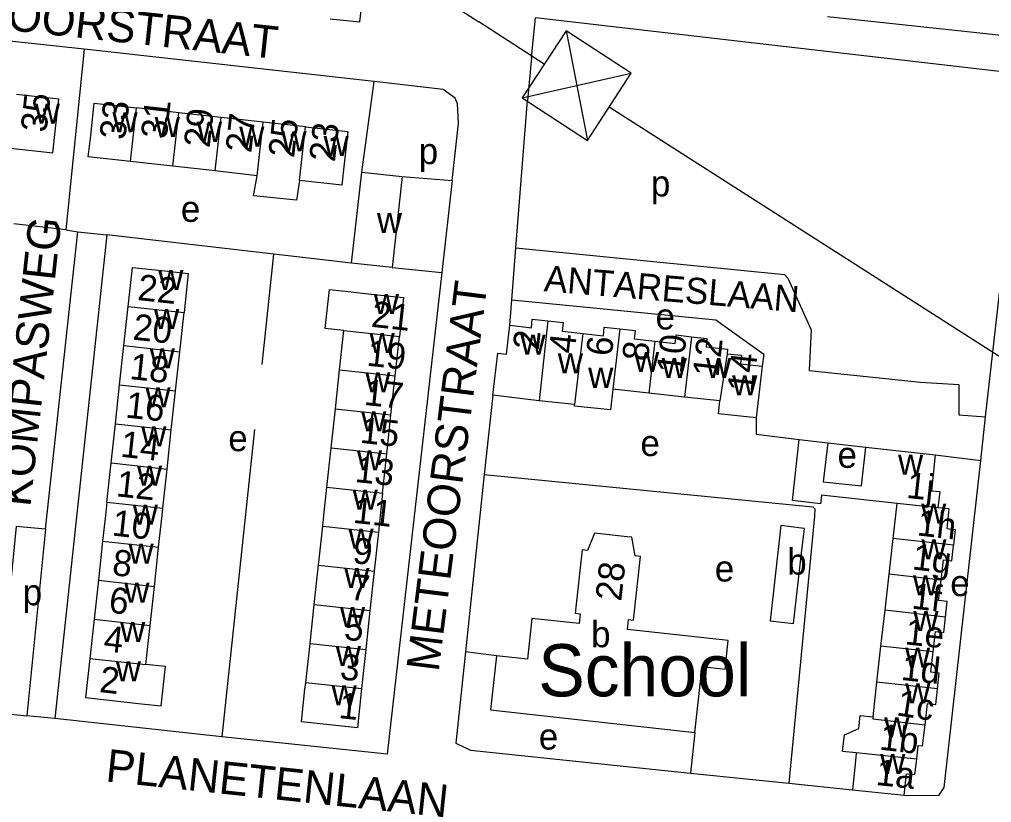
# Model space of a CAD drawing. Extents: x 161936 to 163647, y 386450 to 388633.
# Drawn here: x 162379.9 to 162529.2, y 386956 to 387076.1 of the extents above; entities that cross this region are included whole.
import ezdxf

# ---------------------------------------------------------------- set-up
doc = ezdxf.new("R2010")
doc.units = 0
for name, color, linetype in [('BLT_Basislijn', 7, 'Continuous'), ('BLT_Bebouwing', 7, 'Continuous'), ('BLT_Bebouwing_beschrifting', 7, 'Continuous'), ('BLT_Centroide', 7, 'Continuous'), ('BLT_Hoogspanningsmast_en_leidingen', 7, 'Continuous'), ('BLT_Huisnummer', 7, 'Continuous'), ('BLT_Huisnummer_ tussenligend', 7, 'Continuous'), ('BLT_Onderverdeling_panden', 7, 'Continuous'), ('BLT_Straatnaam', 7, 'Continuous'), ('BLT_Straatnaam_verkleind', 7, 'Continuous')]:
    doc.layers.add(name, color=color, linetype=linetype)

msp = doc.modelspace()

# ---------------------------------------------------------------- linework, layer by layer
at = {"layer": 'BLT_Basislijn'}
for p, q in [((162458.53, 387070.29), (162459.14, 387076.37)), ((162534.16, 387067.72), (162459.14, 387076.37)), ((162503.95, 387076.6), (162534.81, 387073.29)), ((162389.85, 387071.58), (162387.06, 387043.88)), ((162434.36, 387066.62), (162389.85, 387071.58)), ((162458.53, 387070.29), (162457.91, 387063.68)), ((162528.24, 387015.15), (162534.16, 387067.72)), ((162432.48, 387052.73), (162434.36, 387066.62)), ((162456.14, 387041.07), (162457.91, 387063.68)), ((162438.7, 387052.03), (162446.33, 387051.42)), ((162446.33, 387051.42), (162444.75, 387037.3)), ((162387.06, 387043.88), (162379.07, 387044.79)), ((162387.06, 387043.88), (162388.89, 387043.56)), ((162383.91, 386997.91), (162388.89, 387043.56)), ((162393.36, 387043.09), (162385.37, 386968.87)), ((162388.89, 387043.56), (162393.36, 387043.09)), ((162419, 387040.14), (162393.36, 387043.09)), ((162455.52, 387033.09), (162456.14, 387041.07)), ((162417.18, 387023.18), (162419, 387040.14)), ((162430.9, 387038.76), (162419, 387040.14)), ((162437.12, 387038.06), (162444.75, 387037.3)), ((162455.22, 387029.22), (162455.52, 387033.09)), ((162452.62, 387018.51), (162451.29, 387006.33)), ((162416.02, 387013.22), (162411.02, 386966.03)), ((162520.48, 387009.34), (162527.5, 387008.46)), ((162451.29, 387006.33), (162448.39, 386979.09)), ((162383.91, 386997.91), (162381.05, 386969.29)), ((162453.14, 386978.5), (162448.39, 386979.09)), ((162376.57, 386969.75), (162381.05, 386969.29)), ((162385.37, 386968.87), (162381.05, 386969.29)), ((162411.02, 386966.03), (162385.37, 386968.87)), ((162483.61, 386966.71), (162482.95, 386960.5)), ((162482.95, 386960.5), (162498.03, 386958.94)), ((162498.03, 386958.94), (162507.79, 386957.93))]:
    msp.add_line(p, q, dxfattribs=at)
for points in [[(162427.61, 387076.25), (162432.17, 387075.76), (162432.94, 387082.3)], [(162389.85, 387071.58), (162333.1, 387077.67)], [(162446.33, 387051.42), (162447.35, 387060.19), (162447.17, 387063.2), (162446.84, 387064.07), (162444.99, 387065.38), (162434.36, 387066.62)], [(162456.14, 387041.07), (162497.35, 387037), (162497.86, 387036.45), (162501.46, 387028.53), (162501.17, 387022.29), (162518.24, 387020.47), (162524.16, 387020.1), (162524.12, 387015.48), (162528.24, 387015.15)], [(162444.75, 387037.3), (162436.4, 386963.4), (162411.02, 386966.03)], [(162455.52, 387033.09), (162486.85, 387030.05), (162494.21, 387024.76), (162493.94, 387022.93)], [(162493.04, 387014.99), (162493.02, 387012.48), (162499.63, 387011.68)], [(162527.5, 387008.46), (162528.24, 387015.15)], [(162504.03, 387011.19), (162509.84, 387010.49)], [(162515.74, 386957.1), (162521.09, 386957.06), (162521.89, 386958.3), (162527.5, 387008.46)], [(162451.29, 387006.33), (162501.74, 387001.35), (162502.01, 387001.06), (162501.98, 386999.91), (162498.03, 386958.94)], [(162383.91, 386997.91), (162379.42, 386998.33), (162376.57, 386969.75)], [(162448.39, 386979.09), (162446.9, 386965.06), (162449.19, 386964), (162482.95, 386960.5)]]:
    msp.add_lwpolyline(points, dxfattribs=at)
at = {"layer": 'BLT_Bebouwing'}
for p, q in [((162404.39, 387061.83), (162397.9, 387062.56)), ((162410.88, 387061.11), (162404.39, 387061.83)), ((162417.36, 387060.38), (162410.88, 387061.11)), ((162423.85, 387059.65), (162417.36, 387060.38)), ((162403.47, 387053.61), (162396.98, 387054.34)), ((162409.96, 387052.89), (162403.47, 387053.61)), ((162416.44, 387052.16), (162409.96, 387052.89)), ((162430.9, 387038.76), (162432.48, 387052.73)), ((162432.48, 387052.73), (162438.7, 387052.03)), ((162438.7, 387052.03), (162437.12, 387038.06)), ((162437.12, 387038.06), (162430.9, 387038.76)), ((162395.96, 387026.09), (162396.61, 387032.09)), ((162404.55, 387025.15), (162405.2, 387031.15)), ((162429.08, 387022.39), (162429.73, 387028.39)), ((162437.61, 387021.46), (162438.25, 387027.47)), ((162395.3, 387020.09), (162395.96, 387026.09)), ((162403.9, 387019.15), (162404.55, 387025.15)), ((162493.94, 387022.93), (162493.04, 387014.99)), ((162428.43, 387016.39), (162429.08, 387022.39)), ((162436.96, 387015.46), (162437.61, 387021.46)), ((162394.65, 387014.09), (162395.3, 387020.09)), ((162403.24, 387013.15), (162403.9, 387019.15)), ((162476.55, 387018.8), (162471.03, 387019.41)), ((162482.04, 387018.2), (162476.55, 387018.8)), ((162465.16, 387017.03), (162459.71, 387017.63)), ((162487.44, 387017.61), (162482.04, 387018.2)), ((162427.78, 387010.39), (162428.43, 387016.39)), ((162436.32, 387009.46), (162436.96, 387015.46)), ((162394, 387008.09), (162394.65, 387014.09)), ((162402.59, 387007.15), (162403.24, 387013.15)), ((162427.13, 387004.39), (162427.78, 387010.39)), ((162393.35, 387002.09), (162394, 387008.09)), ((162435.67, 387003.46), (162436.32, 387009.46)), ((162401.94, 387001.15), (162402.59, 387007.15)), ((162514.04, 386996.5), (162514.65, 387001.88)), ((162522.61, 387001.02), (162520.9, 387001.2)), ((162425.83, 386992.38), (162426.48, 386998.38)), ((162392.7, 386996.09), (162392.05, 386990.09)), ((162435.03, 386997.46), (162434.38, 386991.46)), ((162513.43, 386991.04), (162514.04, 386996.5)), ((162400.64, 386989.15), (162401.29, 386995.15)), ((162425.18, 386986.38), (162425.83, 386992.38)), ((162392.05, 386990.09), (162391.4, 386984.09)), ((162434.38, 386991.46), (162433.74, 386985.46)), ((162512.81, 386985.5), (162513.43, 386991.04)), ((162399.99, 386983.15), (162400.64, 386989.15)), ((162424.53, 386980.38), (162425.18, 386986.38)), ((162433.74, 386985.46), (162433.09, 386979.45)), ((162512.18, 386979.95), (162512.81, 386985.5)), ((162391.4, 386984.09), (162390.75, 386978.09)), ((162399.34, 386977.15), (162399.99, 386983.15)), ((162423.88, 386974.38), (162424.53, 386980.38)), ((162511.56, 386974.45), (162512.18, 386979.95)), ((162433.09, 386979.45), (162432.44, 386973.45)), ((162510.96, 386969.11), (162511.56, 386974.45)), ((162507.79, 386957.93), (162515.74, 386957.1))]:
    msp.add_line(p, q, dxfattribs=at)
for points in [[(162378.57, 387056.39), (162385.03, 387055.67), (162385.39, 387058.94), (162385.95, 387063.91), (162379.49, 387064.63)], [(162396.98, 387054.34), (162390.49, 387055.06), (162390.86, 387058.31), (162391.41, 387063.28), (162397.9, 387062.56)], [(162423.85, 387059.65), (162430.33, 387058.93), (162429.78, 387053.96), (162429.42, 387050.71), (162422.93, 387051.44)], [(162422.93, 387051.44), (162422.44, 387048.43), (162415.87, 387049.08), (162416.44, 387052.16)], [(162396.61, 387032.09), (162397.26, 387038.09), (162402.23, 387037.55), (162405.85, 387037.15), (162405.2, 387031.15)], [(162429.73, 387028.39), (162426.85, 387028.7), (162427.5, 387034.7), (162430.39, 387034.39), (162433.93, 387034.01), (162438.9, 387033.47), (162438.25, 387027.47)], [(162452.62, 387018.51), (162453.37, 387024.95), (162454.72, 387024.79), (162455.22, 387029.22)], [(162455.22, 387029.22), (162458.51, 387028.84), (162458.65, 387030.14), (162461.03, 387029.88)], [(162461.03, 387029.88), (162463.42, 387029.62), (162463.26, 387028.32), (162466.41, 387027.96)], [(162466.41, 387027.96), (162469.57, 387027.59), (162469.7, 387028.93), (162472.08, 387028.67)], [(162472.08, 387028.67), (162474.46, 387028.42), (162474.31, 387027.12), (162477.45, 387026.78)], [(162477.45, 387026.78), (162480.59, 387026.44), (162480.72, 387027.72), (162483.09, 387027.44)], [(162483.09, 387027.44), (162485.47, 387027.17), (162485.36, 387025.88), (162488.61, 387025.52), (162488.57, 387024.82)], [(162488.57, 387024.82), (162490.78, 387024.6), (162490.64, 387023.3), (162493.94, 387022.93)], [(162459.71, 387017.63), (162452.62, 387018.51)], [(162471.03, 387019.41), (162470.67, 387016.21), (162465.15, 387016.81), (162465.16, 387017.03)], [(162493.04, 387014.99), (162487.22, 387015.62), (162487.44, 387017.61)], [(162498.6, 387002.32), (162499.63, 387011.68)], [(162499.63, 387011.68), (162504.03, 387011.19)], [(162504.03, 387011.19), (162503.3, 387005.17), (162509.2, 387004.59), (162509.84, 387010.49)], [(162509.84, 387010.49), (162520.48, 387009.34)], [(162520.48, 387009.34), (162519.93, 387003.82), (162521.22, 387003.7), (162520.9, 387001.2)], [(162426.48, 386998.38), (162426.66, 387000), (162427.13, 387004.39)], [(162393.35, 387002.09), (162393.12, 387000), (162392.7, 386996.09)], [(162435.67, 387003.46), (162435.3, 387000), (162435.03, 386997.46)], [(162514.65, 387001.88), (162503.05, 387003.14), (162502.89, 387001.81), (162498.6, 387002.32)], [(162401.29, 386995.15), (162401.82, 387000), (162401.94, 387001.15)], [(162522.61, 387001.02), (162522.51, 387000), (162522.3, 386998.01), (162523.57, 386997.87), (162523.31, 386995.48)], [(162500, 386998.1), (162496.81, 386998.46), (162495.17, 386983.87), (162498.78, 386983.47), (162500, 386994.25), (162500.43, 386998.05), (162500, 386998.1)], [(162473.27, 386982.53), (162473.44, 386984.05), (162474.17, 386983.97), (162475.25, 386993.72), (162474.43, 386993.81), (162473.93, 386996.67), (162473.2, 386996.76), (162468.23, 386997.3), (162467.15, 386994.66), (162466.29, 386994.75), (162465.22, 386985.01), (162466.02, 386984.92), (162465.86, 386983.43)], [(162521.4, 386990.1), (162521.77, 386993.21), (162523.04, 386993.08), (162523.31, 386995.48)], [(162522.08, 386984.44), (162522.36, 386986.83), (162521.03, 386986.99), (162521.4, 386990.1)], [(162465.86, 386983.43), (162458.6, 386984.23), (162457.91, 386977.98), (162453.14, 386978.5)], [(162520.19, 386979.09), (162520.53, 386982.21), (162521.81, 386982.05), (162522.08, 386984.44)], [(162483.61, 386966.71), (162484.72, 386976.83), (162488.26, 386976.44), (162488.74, 386980.83), (162473.27, 386982.53)], [(162453.14, 386978.5), (162452.23, 386970.22), (162483.61, 386966.71)], [(162520.88, 386973.42), (162521.14, 386975.8), (162519.86, 386975.97), (162520.19, 386979.09)], [(162390.75, 386978.09), (162390.09, 386972.08), (162398.68, 386971.12), (162401.68, 386970.79), (162402.34, 386976.83), (162399.34, 386977.15)], [(162432.44, 386973.45), (162431.8, 386967.45), (162423.23, 386968.38), (162423.76, 386973.35), (162423.88, 386974.38)], [(162518.95, 386967.92), (162519.32, 386971.18), (162520.62, 386971.04), (162520.88, 386973.42)], [(162508.38, 386963.61), (162506.29, 386963.83), (162506.56, 386966.36), (162508.77, 386967.31), (162508.97, 386969.32), (162510.96, 386969.11)], [(162517.67, 386962.63), (162517.91, 386964.73), (162518.57, 386964.65), (162518.95, 386967.92)], [(162508.38, 386963.61), (162508.31, 386962.9), (162507.79, 386957.93)], [(162515.74, 386957.1), (162516.09, 386960.4), (162517.4, 386960.26), (162517.67, 386962.63)]]:
    msp.add_lwpolyline(points, dxfattribs=at)
at = {"layer": 'BLT_Hoogspanningsmast_en_leidingen'}
for p, q in [((162209.53, 387230.13), (162450.47, 387075.79)), ((162460.47, 387069.27), (162450.47, 387075.79)), ((162463.83, 387074.42), (162467.11, 387057.59)), ((162457.11, 387064.11), (162473.83, 387067.9)), ((162470.47, 387062.75), (162726.36, 386899.12))]:
    msp.add_line(p, q, dxfattribs=at)
msp.add_lwpolyline([(162463.83, 387074.42), (162457.11, 387064.11), (162467.11, 387057.59), (162473.83, 387067.9)], close=True, dxfattribs=at)
at = {"layer": 'BLT_Onderverdeling_panden'}
for p, q in [((162396.98, 387054.34), (162397.9, 387062.56)), ((162403.47, 387053.61), (162404.39, 387061.83)), ((162409.96, 387052.89), (162410.88, 387061.11)), ((162416.44, 387052.16), (162417.36, 387060.38)), ((162422.93, 387051.44), (162423.85, 387059.65)), ((162396.61, 387032.09), (162405.2, 387031.15)), ((162461.03, 387029.88), (162459.71, 387017.63)), ((162429.73, 387028.39), (162438.25, 387027.47)), ((162466.41, 387027.96), (162465.16, 387017.03)), ((162472.08, 387028.67), (162471.03, 387019.41)), ((162483.09, 387027.44), (162482.04, 387018.2)), ((162395.96, 387026.09), (162404.55, 387025.15)), ((162477.45, 387026.78), (162476.55, 387018.8)), ((162488.57, 387024.82), (162487.44, 387017.61)), ((162429.08, 387022.39), (162437.61, 387021.46)), ((162395.3, 387020.09), (162403.9, 387019.15)), ((162428.43, 387016.39), (162436.96, 387015.46)), ((162394.65, 387014.09), (162403.24, 387013.15)), ((162427.78, 387010.39), (162436.32, 387009.46)), ((162394, 387008.09), (162402.59, 387007.15)), ((162427.13, 387004.39), (162435.67, 387003.46)), ((162393.35, 387002.09), (162401.94, 387001.15)), ((162520.9, 387001.2), (162514.65, 387001.88)), ((162426.48, 386998.38), (162435.03, 386997.46)), ((162392.7, 386996.09), (162401.29, 386995.15)), ((162523.31, 386995.48), (162514.04, 386996.5)), ((162425.83, 386992.38), (162434.38, 386991.46)), ((162392.05, 386990.09), (162400.64, 386989.15)), ((162521.4, 386990.1), (162513.43, 386991.04)), ((162425.18, 386986.38), (162433.74, 386985.46)), ((162522.08, 386984.44), (162512.81, 386985.5)), ((162391.4, 386984.09), (162399.99, 386983.15)), ((162424.53, 386980.38), (162433.09, 386979.45)), ((162520.19, 386979.09), (162512.18, 386979.95)), ((162390.75, 386978.09), (162399.34, 386977.15)), ((162423.88, 386974.38), (162432.44, 386973.45)), ((162520.88, 386973.42), (162511.56, 386974.45)), ((162517.67, 386962.63), (162508.38, 386963.61))]:
    msp.add_line(p, q, dxfattribs=at)
msp.add_lwpolyline([(162510.96, 386969.11), (162510.93, 386968.84), (162518.95, 386967.92)], dxfattribs=at)

# ---------------------------------------------------------------- texts
at = {"layer": 'BLT_Bebouwing_beschrifting'}
msp.add_text('School', height=8, dxfattribs=at).set_placement((162459.57, 386972.27))
at = {"layer": 'BLT_Centroide'}
for s, p in [('w', (162382.27, 387060.14)), ('w', (162394.2, 387058.81)), ('w', (162400.69, 387058.09)), ('w', (162407.17, 387057.36)), ('w', (162413.66, 387056.62)), ('w', (162420.14, 387055.91)), ('w', (162426.62, 387055.19)), ('p', (162441.23, 387053.94)), ('p', (162476.87, 387048.98)), ('e', (162404.71, 387045.08)), ('w', (162434.8, 387043.39)), ('w', (162401.23, 387034.62)), ('w', (162434.32, 387030.94)), ('w', (162400.58, 387028.62)), ('e', (162477.58, 387028.57)), ('w', (162433.67, 387024.94)), ('w', (162456.83, 387024.72)), ('w', (162399.92, 387022.62)), ('w', (162462.57, 387021.82)), ('w', (162474.27, 387022.06)), ('w', (162478.52, 387021.13)), ('w', (162485.33, 387021.13)), ('w', (162433.02, 387018.94)), ('w', (162467.23, 387019.61)), ('w', (162489.34, 387018.45)), ('w', (162399.27, 387016.62)), ('w', (162432.38, 387012.94)), ('w', (162398.62, 387010.62)), ('e', (162411.99, 387009.89)), ('e', (162475.26, 387009.14)), ('w', (162431.73, 387006.94)), ('e', (162505.52, 387007.33)), ('w', (162514.8, 387006.28)), ('w', (162397.97, 387004.62)), ('w', (162431.07, 387000.91)), ('w', (162397.32, 386998.62)), ('w', (162518.34, 386998.78)), ('w', (162430.43, 386994.91)), ('w', (162518.38, 386993.31)), ('w', (162396.67, 386992.62)), ('b', (162497.8, 386990.95)), ('w', (162429.78, 386988.91)), ('e', (162486.67, 386989.89)), ('w', (162517.09, 386987.75)), ('e', (162522.82, 386987.65)), ('p', (162380.43, 386986.24)), ('w', (162396.02, 386986.62)), ('w', (162429.13, 386982.91)), ('w', (162517.15, 386982.28)), ('w', (162395.37, 386980.62)), ('b', (162467.69, 386979.81)), ('w', (162428.48, 386976.91)), ('w', (162515.88, 386976.69)), ('w', (162394.72, 386974.59)), ('w', (162427.84, 386970.91)), ('w', (162515.91, 386971.19)), ('w', (162512.68, 386965.97)), ('e', (162459.66, 386964.1)), ('w', (162512.06, 386960.34))]:
    msp.add_text(s, height=4, dxfattribs=at).set_placement(p)
at = {"layer": 'BLT_Huisnummer'}
for s, rotation, p in [('35', 83.6142, (162384.06, 387058.71)), ('33', 83.6185, (162396.16, 387057.58)), ('27', 83.6185, (162415.51, 387055.57)), ('23', 83.6269, (162428.35, 387054.17)), ('22', 353.8084, (162397.94, 387033.1)), ('21', 353.8111, (162433.82, 387028.99)), ('2', 83.8553, (162459.63, 387025.29)), ('10', 83.4769, (162481.69, 387021.67)), ('6', 83.7898, (162470.86, 387024.36)), ('18', 353.8084, (162396.74, 387020.97)), ('14', 83.5608, (162492.56, 387018.82)), ('17', 353.8117, (162432.73, 387017.01)), ('14', 353.8084, (162395.32, 387009.05)), ('13', 353.8087, (162431.33, 387005.18)), ('1j', 353.8258, (162515.98, 387002.74)), ('10', 353.8077, (162394.02, 386996.96)), ('9', 353.8123, (162430.95, 386992.73)), ('1g', 353.2814, (162516.86, 386991.77)), ('28', 83.7158, (162472.31, 386986.77)), ('6', 353.8077, (162393.53, 386985.12)), ('5', 353.8091, (162429.64, 386980.98)), ('1e', 353.8711, (162515.76, 386980.26)), ('2', 353.6283, (162392.09, 386972.94)), ('1', 353.8359, (162428.83, 386968.95)), ('1c', 350.942, (162514.43, 386969.38)), ('1a', 354.0592, (162511.28, 386958.68))]:
    msp.add_text(s, height=4, rotation=rotation, dxfattribs=at).set_placement(p)
at = {"layer": 'BLT_Huisnummer_ tussenligend'}
for s, rotation, p in [('31', 83.6185, (162402.51, 387057.69)), ('29', 83.6185, (162409.11, 387056.35)), ('25', 83.6269, (162422.08, 387054.81)), ('20', 353.8084, (162397.22, 387027.02)), ('4', 83.8553, (162465.16, 387024.76)), ('19', 353.8117, (162433.13, 387023.03)), ('8', 83.7898, (162476.4, 387023.59)), ('12', 83.4769, (162487.23, 387021.17)), ('16', 353.8084, (162396.09, 387015.07)), ('15', 353.8087, (162432.1, 387011.19)), ('12', 353.8077, (162394.67, 387002.98)), ('11', 353.8123, (162431.03, 386998.91)), ('1h', 353.7094, (162517.61, 386996.98)), ('8', 353.8077, (162394.05, 386990.88)), ('7', 353.8091, (162430.52, 386987.12)), ('1f', 353.4924, (162516.78, 386985.75)), ('4', 353.6283, (162392.72, 386979.21)), ('3', 353.8359, (162429.02, 386974.88)), ('1d', 353.7132, (162515.15, 386974.8)), ('1b', 353.4295, (162511.83, 386964.11))]:
    msp.add_text(s, height=4, rotation=rotation, dxfattribs=at).set_placement(p)
at = {"layer": 'BLT_Straatnaam'}
for s, rotation, p in [('METEOORSTRAAT', 353.8343, (162359.49, 387076.53)), ('KOMPASWEG', 83.8221, (162381.59, 387001.24)), ('METEOORSTRAAT', 82.8343, (162444.27, 386975.92)), ('PLANETENLAAN', 353.9595, (162393.03, 386959.23))]:
    msp.add_text(s, height=5, rotation=rotation, dxfattribs=at).set_placement(p)
at = {"layer": 'BLT_Straatnaam_verkleind'}
msp.add_text('ANTARESLAAN', height=3.9999, rotation=355.244, dxfattribs=at).set_placement((162460.36, 387034.45))

doc.saveas('drawing.dxf')
